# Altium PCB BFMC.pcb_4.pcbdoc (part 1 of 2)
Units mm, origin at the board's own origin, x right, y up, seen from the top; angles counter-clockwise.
Board outline 140.08 x 106.48 mm, 2 copper layers (Top Layer, Bottom Layer); 130 components, 63 nets, 367 pads, 103 vias.
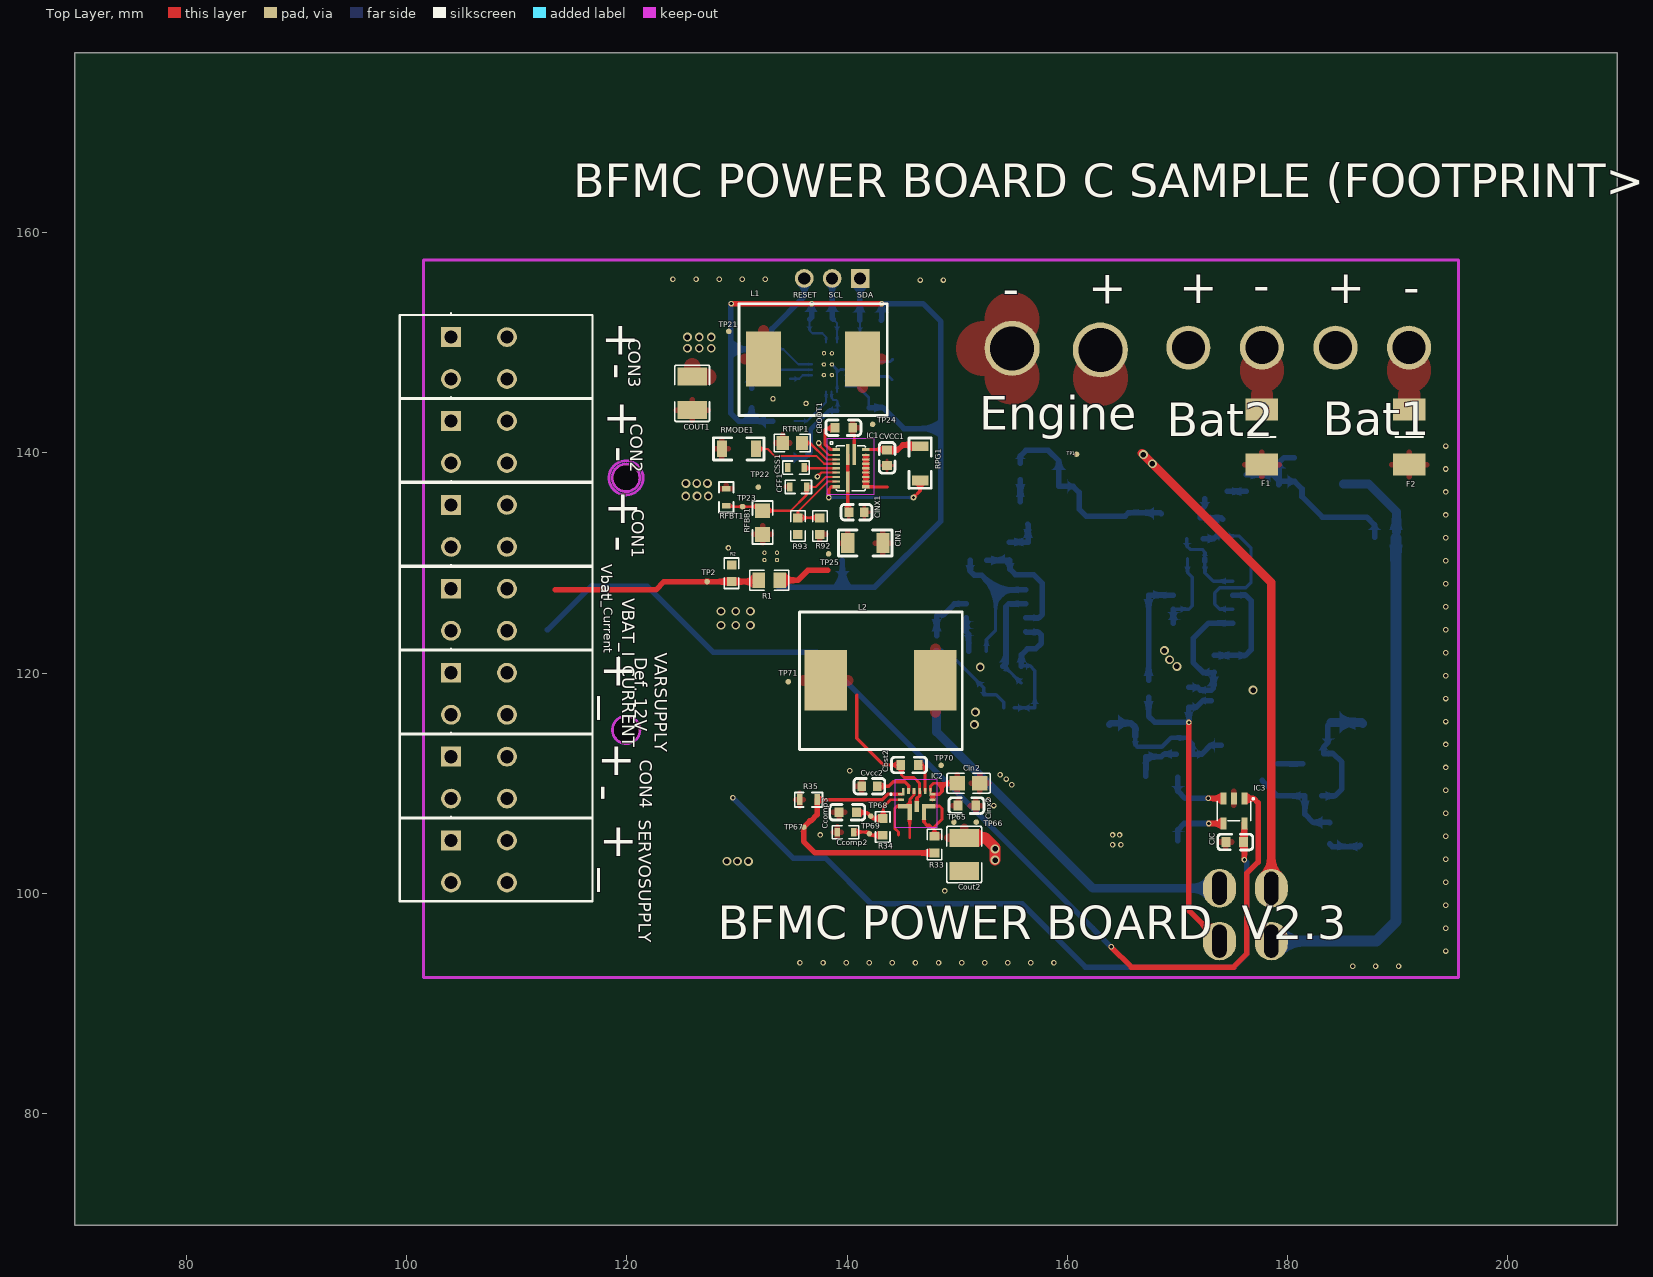
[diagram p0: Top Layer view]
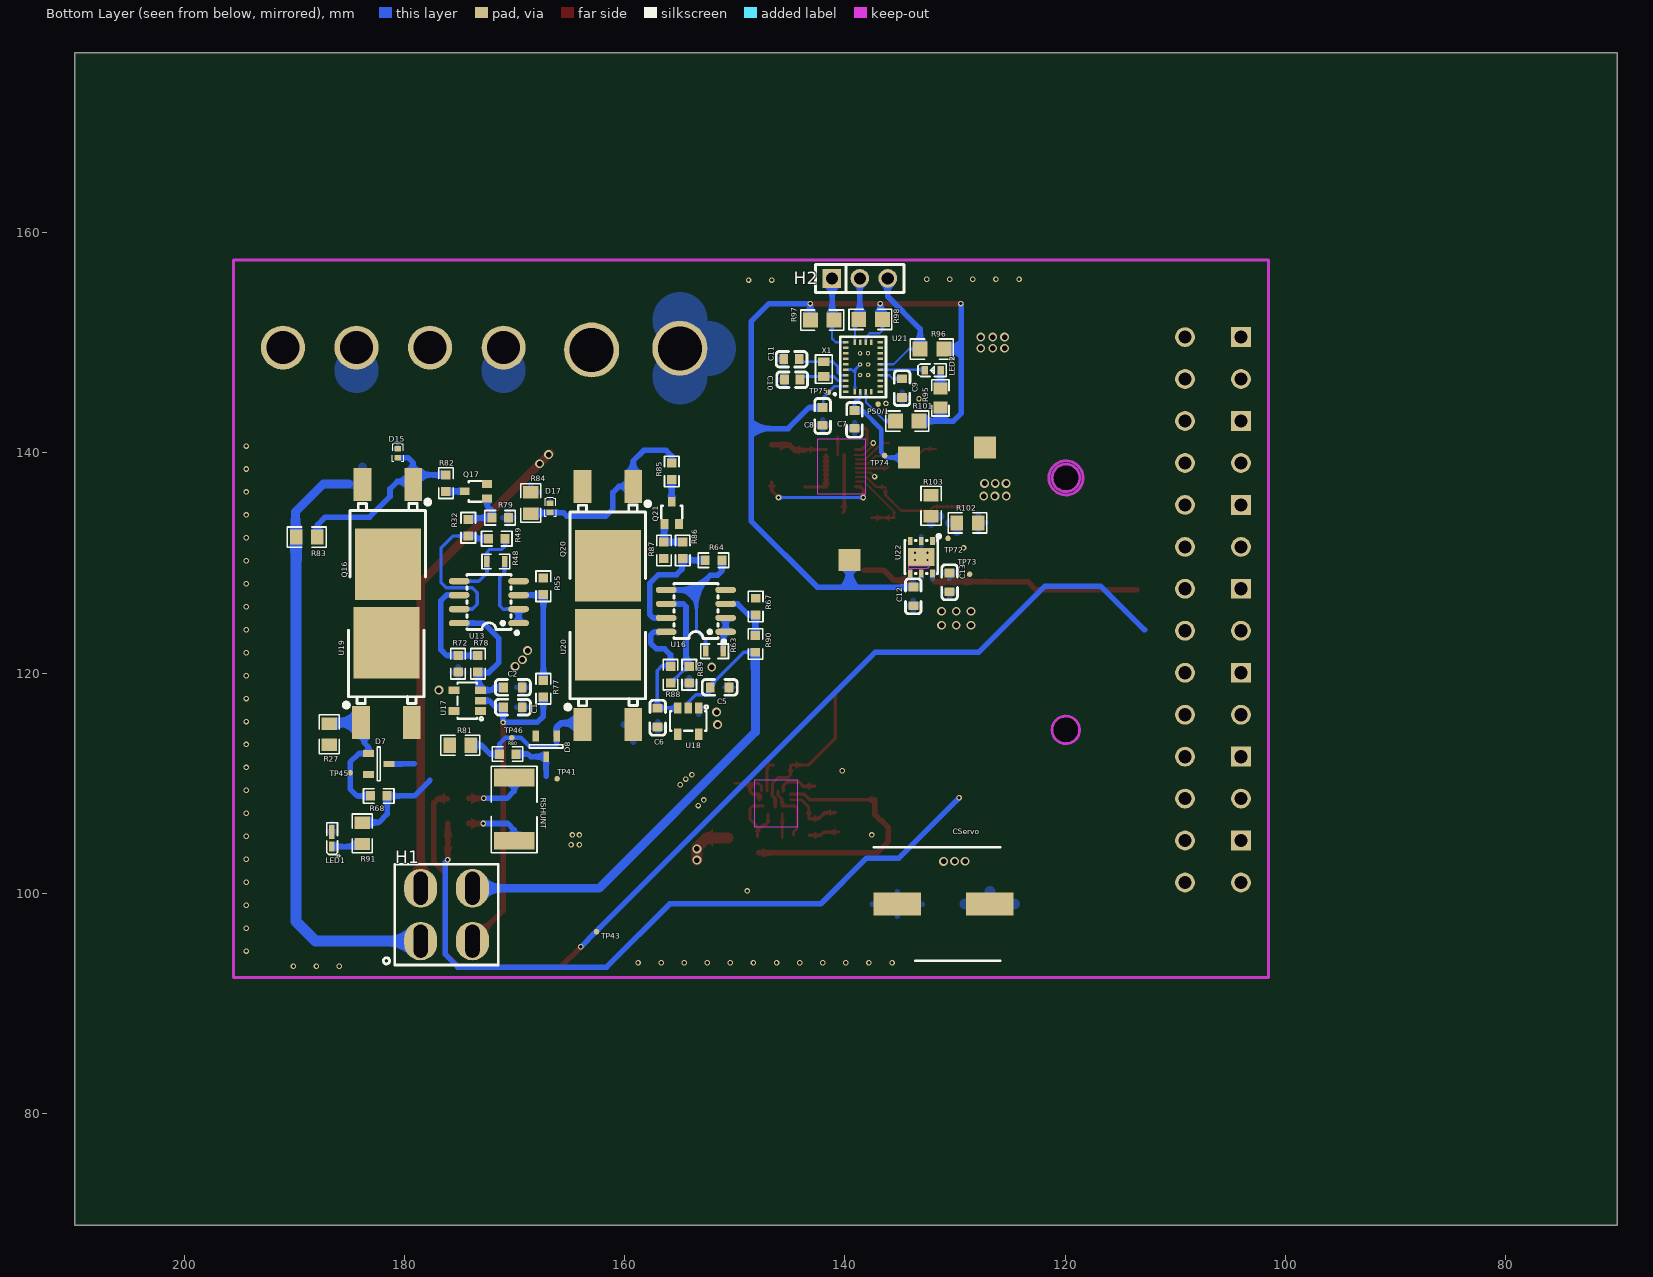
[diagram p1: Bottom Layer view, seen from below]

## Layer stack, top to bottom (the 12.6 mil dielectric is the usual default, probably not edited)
Top Layer: signal copper (thickness not stored)
Dielectric: dielectric 0.32, FR-4, Dk 4.8
Bottom Layer: signal copper (thickness not stored)

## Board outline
209.93,69.85 69.85,69.85 69.85,176.33 209.93,176.33
cut-out: 121.165,137.723 ccw(c119.915,137.711) 118.665,137.723 ccw(c119.915,137.735)
cut-out: 121.182,114.836 ccw(c119.932,114.836) 118.682,114.836 ccw(c119.932,114.836)

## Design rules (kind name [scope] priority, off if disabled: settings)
Clearance copperThickness1oz [All] p1: gap=0.178 ignorepadtopadclearanceinfootprint=FALSE except(0.102: Track-Track; 0.152: Track-SMDPad SMDPad-SMDPad Track-THPad SMDPad-THPad THPad-THPad Track-Via SMDPad-Via THPad-Via Via-Via Track-Fill SMDPad-Fill THPad-Fill Via-Fill Fill-Fill SMDPad-Region THPad-Region Via-Region Fill-Region Region-Region Track-Poly SMDPad-Poly THPad-Poly Via-Poly Fill-Poly Poly-Poly Track-Text SMDPad-Text THPad-Text Via-Text Fill-Text Region-Text Poly-Text Text-Text Track-Hole SMDPad-Hole THPad-Hole Via-Hole Fill-Hole Region-Hole Poly-Hole Text-Hole; 0.3: Track-Region Region-Poly Track-Sheet SMDPad-Sheet THPad-Sheet Via-Sheet Fill-Sheet Region-Sheet Poly-Sheet Text-Sheet Sheet-Hole)
Clearance copperThickness2oz [All] p1: gap=0.178 ignorepadtopadclearanceinfootprint=FALSE except(0.152: Track-SMDPad SMDPad-SMDPad Track-THPad SMDPad-THPad THPad-THPad Track-Via SMDPad-Via THPad-Via Via-Via Track-Fill SMDPad-Fill THPad-Fill Via-Fill Fill-Fill SMDPad-Region THPad-Region Via-Region Fill-Region Region-Region Track-Poly SMDPad-Poly THPad-Poly Via-Poly Fill-Poly Poly-Poly Track-Text SMDPad-Text THPad-Text Via-Text Fill-Text Region-Text Poly-Text Text-Text Track-Hole SMDPad-Hole THPad-Hole Via-Hole Fill-Hole Region-Hole Poly-Hole Text-Hole; 0.203: Track-Track; 0.3: Track-Region Region-Poly Track-Sheet SMDPad-Sheet THPad-Sheet Via-Sheet Fill-Sheet Region-Sheet Poly-Sheet Text-Sheet Sheet-Hole)
Clearance Supply-GND [All] p1: gap=0.178 ignorepadtopadclearanceinfootprint=FALSE except(0.5: Track-Track Track-SMDPad SMDPad-SMDPad Track-THPad SMDPad-THPad THPad-THPad Track-Via SMDPad-Via THPad-Via Via-Via Track-Fill SMDPad-Fill THPad-Fill Via-Fill Fill-Fill Track-Region SMDPad-Region THPad-Region Via-Region Fill-Region Region-Region Track-Poly SMDPad-Poly THPad-Poly Via-Poly Fill-Poly Region-Poly Poly-Poly Track-Text SMDPad-Text THPad-Text Via-Text Fill-Text Region-Text Poly-Text Text-Text Track-Sheet SMDPad-Sheet THPad-Sheet Via-Sheet Fill-Sheet Region-Sheet Poly-Sheet Text-Sheet Track-Hole SMDPad-Hole THPad-Hole Via-Hole Fill-Hole Region-Hole Poly-Hole Text-Hole Sheet-Hole)
DiffPairsRouting differentialPair [All] p1: maxuncoupledlength=10 maxlimit=5.9843 mostfreqgap=5.9843 toplayer_minwidth=5 toplayer_prefwidth=10 toplayer_maxwidth=100 bottomlayer_minwidth=5 bottomlayer_prefwidth=10 bottomlayer_maxwidth=100
PasteMaskExpansion pasteMaskExpansion [All] p1:
PlaneConnect innerPlane [All] p1: planeconnectstyle=Relief reliefexpansion=0.508 reliefentries=4 reliefconductorwidth=0.254 reliefairgap=0.254
PolygonConnect copperRegion [All] p1: connectstyle=Direct reliefentries=4 reliefconductorwidth=10 polygonreliefangle="90 Angle" airgapwidth=10
PolygonConnect copperRegion1 [All] p1: connectstyle=Relief reliefentries=4 reliefconductorwidth=10 polygonreliefangle="90 Angle" airgapwidth=10
PolygonConnect copperRegion2 [All] p1: connectstyle=Relief reliefentries=4 reliefconductorwidth=10 polygonreliefangle="90 Angle" airgapwidth=10
RoutingVias viaSize [All] p1: viastyle="Through Hole" holewidth=12.0078 minholewidth=11.811 maxholewidth=248.0314 width=24.0158 minwidth=19.685 maxwidth=393.7008
SolderMaskExpansion solderMaskExpansion [All] p1: useseparateexpansions=TRUE expansion=2.0079 expansionbottom=2.0079
Width copperThickness1oz [All] p1: maxlimit=100 minlimit=5 preferedwidth=10
Width copperThickness2oz [All] p1: maxlimit=100 minlimit=8 preferedwidth=10

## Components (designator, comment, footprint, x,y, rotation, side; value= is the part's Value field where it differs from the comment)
C1 "CAP_0201" C9 170.196,116.895 r180 bottom
C2 "CAP_0201" C9 170.196,118.695 r180 bottom
C5 "CAP_0201" C9 151.416,118.695 r180 bottom
C6 "CAP_0201" C9 156.996,115.995 r270 bottom
C7 "CAP_0201" Cbst2 139.116,142.935 r90 bottom
C8 "CAP_0201" Cbst2 142.02,143.4 r270 bottom
C9 "CAP_0201" C9 134.796,145.815 r90 bottom
C10 "CAP_0201" C0603 144.78,146.64 r0 bottom
C11 "CAP_0201" C0603 144.84,148.5 r0 bottom
C12 "CAP_0201" C9 133.776,126.915 r90 bottom
C13 "CAP_0201" C9 130.476,128.189 r90 bottom
CBOOT1 "EMK105 B7104KVHF" Cbst2 139.596,142.275 r0 top
Cbst2 "CAP_0201" Cbst2 145.559,111.645 r0 top
Ccomp2 "CAP_0201" "0603 0.5x0.8" 139.844,105.549 r0 top
Ccomp3 "CAP_0201" Cbst2 139.956,107.355 r0 top
CFF1 "C1005C0G1H220J" "0603 0.5x0.8" 135.557,136.904 r0 top
CIC "C2012X7S1C106K" Cbst2 175.296,104.655 r180 top
CIN1 "GCJ31CC71E106K" "Cin1 Aditome" 141.741,131.807 r0 top
Cin2 "CAP_0201" c0805 151.02,109.994 r180 top
CINX1 "GCM188C71A225K" C0603 140.852,134.601 r0 top
Cinx2 "CAP_0201" Cbst2 150.766,107.962 r0 top
CON1 "switch" "new connector" 106.56,133.361 r270 top
CON2 "switch" "new connector" 106.56,140.981 r270 top
CON3 "switch" "new connector" 106.56,148.601 r270 top
CON4 "switch" "new connector" 106.56,110.501 r270 top
COUT1 "EMK325ABJ107MM-T" C1210 125.919,145.4 r270 top
Cout2 "CAP_0201" C1210 150.626,103.519 r90 top
CServo "GCM188C71A225K" CAPAE1030X1050N 131.033,99.022 r180 bottom
CSS1 "C1608X7R1H154K" "0603 0.5x0.8" 135.353,138.657 r180 top
CVCC1 "GCM188C71A225K" C0603 143.619,139.54 r270 top
Cvcc2 "CAP_0201" C0603 142.026,109.719 r0 top
D7 "SZBZX84C18ET1G" SZBZX84C18ET1G 182.319,111.74 r270 bottom
D8 "SZBZX84C18ET1G" SZBZX84C18ET1G 167.119,113.34 r0 bottom
D15 "PZU6.8B2L,315" DFN1006-2L-RD 180.608,139.965 r270 bottom
D17 "PZU6.8B2L,315" DFN1006-2L-RD 166.765,135.012 r270 bottom
F1 "0451015.MRL" FUSC6127X294N 177.66,141.436 r270 top
F2 "0451015.MRL" FUSC6127X294N 191.047,141.436 r270 top
H1 "switch" M2021BB1W01 176.163,98.055 r0 bottom
H2 "HDR-M_2.54_1x3P" HDR-TH_3P-P2.54-V-M 138.636,155.835 r180 bottom
IC1 "TPS548A28RWWR" TPS548B28RWWR 140.344,138.603 r0 top
IC2 "TPS61288RQQR" TPS61288RQQR 146.326,108.119 r0 top
IC3 "INA180A2QDBVRQ1" ina180a2qdbvrq1 175.116,107.475 r180 top
L1 "IHLP4040DZERR47M11" IHLP4040DZERR47M11 136.896,148.455 r0 top
L2 "L_0402" "DR127-3R3-R (L2)" 143.026,119.332 r0 top
LED1 "19-213/Y2C-CQ2R2L/3T(CY)" LEDGREEN 186.576,105.015 r90 bottom
LED2 "TLMS1100-GS08" "LED2 RED" 132.096,147.495 r180 bottom
PS0/1 "Test-Point" Test-Point-0.5mm 136.98,144.42 r180 bottom
Q16 "IPD50P04P4-13" pg-to252-3_l6.3-w6.5-p4.57-ls10.0-br-cw 181.497,133.488 r90 bottom
Q17 "BC846W" SOT-323-3_L2.2-W1.3-P1.30-LS2.2-BR 173.499,136.5 r180 bottom
Q20 "IPD50P04P4-13" pg-to252-3_l6.3-w6.5-p4.57-ls10.0-br-cw 161.519,133.34 r90 bottom
Q21 "BC846W" SOT-323-3_L2.2-W1.3-P1.30-LS2.2-BR 155.719,134.54 r270 bottom
R1 "MCR03..PFX1051" R0805_NEW 132.923,128.425 r0 top
R2 "MCR03...PFX7680" r0603_new 129.494,129.06 r90 top
R27 "MCR03..PFX1002" R0805_NEW 186.819,114.44 r270 bottom
R32 "MCR03..PFX1002" R0603 174.199,133.2 r90 bottom
R33 "MCR03..PFX1002" R0603 147.926,104.419 r90 top
R34 "MCR03..PFX1002" R0603 143.226,106.019 r90 top
R35 "MCR03..PFX1002" R35 136.476,108.495 r180 top
R48 "Res_0603" R35 171.7,130.14 r0 bottom
R49 "Res_0603" R0603 171.599,132.2 r0 bottom
R55 "Res_0603" R0603 167.376,127.875 r270 bottom
R63 "Res_0603" R35 151.84,121.98 r0 bottom
R64 "Res_0603" R0603 151.919,130.24 r0 bottom
R67 "Res_0603" R0603 148.092,126.04 r270 bottom
R68 "Res_0603" R0603 182.319,108.84 r180 bottom
R72 "Res_0603" R0603 175.119,120.84 r270 bottom
R77 "Res_0603" R0603 167.376,118.575 r270 bottom
R78 "Res_0603" R0603 173.319,120.84 r270 bottom
R79 "Res_0603" R0603 171.299,134.1 r0 bottom
R80 "Res_0603" R0603 170.619,112.64 r180 bottom
R81 "MCR03..PFX1002" R0805_NEW 174.919,113.44 r0 bottom
R82 "Res_0603" R0603 176.216,137.242 r90 bottom
R83 "MCR03..PFX1002" R0805_NEW 188.863,132.345 r0 bottom
R84 "MCR03..PFX1002" R0805_NEW 168.519,135.44 r90 bottom
R85 "Res_0603" R0603 155.716,138.314 r90 bottom
R86 "MCR03..PFX1002" R0603 154.719,131.14 r270 bottom
R87 "Res_0603" R0603 156.419,131.14 r90 bottom
R88 "Res_0603" R0603 155.819,119.84 r270 bottom
R89 "Res_0603" R0603 154.119,119.84 r270 bottom
R90 "Res_0603" R0603 148.119,122.64 r90 bottom
R91 "Res_0603" R0805_NEW 183.819,105.44 r90 bottom
R92 "Res_0603" R0603 137.519,133.34 r270 top
R93 "Res_0603" R0603 135.519,133.34 r90 top
R95 "Res_0201" Rtrip 131.316,144.855 r90 bottom
R96 "Res_0201" "0805 dany2" 132.156,149.415 r180 bottom
R97 "Res_0201" "0805 dany2" 142.116,152.055 r180 bottom
R98 "Res_0201" "0805 dany2" 137.736,152.115 r180 bottom
R101 "Res_0201" "0805 dany2" 134.256,142.875 r0 bottom
R102 "Res_0201" R0805_NEW 128.856,133.635 r0 bottom
R103 "Res_0201" R0805_NEW 132.156,135.195 r90 bottom
RFBB1 "SMM0204 50 10K 1 %" "0805 dany2" 132.319,133.74 r270 top
RFBT1 "SMM0204 50 73K2 1 %" "0603 0.5x0.8" 129.019,135.96 r270 top
RMODE1 "SMM0204 50 30K1 1 %" "1206R aditome" 130.176,140.355 r180 top
RPG1 "SMM0204 50 30K1 1 %" "1206R aditome" 146.619,139.04 r90 top
RSHUNT "WSLP25122L500FEA" "WSLP25122L000FEA BUN" 170.019,107.64 r270 bottom
RTRIP1 "SMM0204 50 7K32 1 %" Rtrip 135.142,140.889 r180 top
SERVOSUPPLY "switch" "new connector" 106.56,102.881 r270 top
TP1 "Test-Point" Test-Point-0.5mm 160.824,139.862 r180 top
TP2 "Test-Point" Test-Point-0.5mm 127.275,128.302 r0 top
TP21 "Test-Point" Test-Point-0.5mm 129.244,151.024 r0 top
TP22 "Test-Point" Test-Point-0.5mm 131.924,136.887 r0 top
TP23 "Test-Point" Test-Point-0.5mm 130.502,135.109 r90 top
TP24 "Test-Point" Test-Point-0.5mm 142.306,142.586 r270 top
TP25 "Test-Point" Test-Point-0.5mm 138.306,130.821 r0 top
TP41 "Test-Point" Test-Point-0.5mm 166.127,110.398 r180 bottom
TP43 "Test-Point" Test-Point-0.5mm 162.546,96.516 r180 bottom
TP45 "Test-Point" Test-Point-0.5mm 184.919,110.94 r180 bottom
TP46 "Test-Point" Test-Point-0.5mm 170.246,114.114 r180 bottom
TP65 "Test-Point" Test-Point-0.5mm 149.694,106.459 r0 top
TP66 "Test-Point" Test-Point-0.5mm 151.718,106.457 r270 top
TP67 "Test-Point" Test-Point-0.5mm 136.057,106.01 r0 top
TP68 "Test-Point" Test-Point-0.5mm 142.141,107.01 r0 top
TP69 "Test-Point" Test-Point-0.5mm 142.019,105.408 r0 top
TP70 "Test-Point" Test-Point-0.5mm 148.526,111.619 r270 top
TP71 "Test-Point" Test-Point-0.5mm 134.65,119.211 r0 top
TP72 "Test-Point" Test-Point-0.5mm 130.627,132.227 r180 bottom
TP73 "Test-Point" Test-Point-0.5mm 128.667,128.967 r180 bottom
TP74 "Test-Point" Test-Point-0.5mm 136.38,139.74 r180 bottom
TP75 "Test-Point" Test-Point-0.5mm 141.48,145.5 r180 bottom
U13 "LT1490IS8#PBF" SO-8_L4.9-W3.9-P1.27-LS5.9-BL 172.319,126.44 r90 bottom
U16 "LT1490IS8#PBF" SO-8_L4.9-W3.9-P1.27-LS5.9-BL 153.519,125.64 r90 bottom
U17 "NCP715SN50T1G" TSOP-5_L3.0-W1.5-P0.95-BL 174.276,117.495 r90 bottom
U18 "NCP715SN50T1G" TSOP-5_L3.0-W1.5-P0.95-BL 154.219,115.64 r0 bottom
U19 "DMPH3010LK3-13" pg-to252-3_l6.3-w6.5-p4.57-ls10.0-br-cw 181.634,119.127 r270 bottom
U20 "DMPH3010LK3-13" pg-to252-3_l6.3-w6.5-p4.57-ls10.0-br-cw 161.519,118.94 r270 bottom
U21 "BNO055" LGA-28_L5.2-W3.8-P0.50-BL 138.336,147.795 r180 bottom
U22 "NCP708MU330TAG" DFN-6_L3.0-W3.0-P0.95-LS3.1-BL-EP 133.056,130.515 r0 bottom
VARSUPPLY "switch" "new connector" 106.56,118.121 r270 top
VBAT_I_CURRENT "switch" "new connector" 106.56,125.741 r270 top
X1 "ABS05-32.768kHz-T" OSC-SMD_2P-L1.6-W1.0 141.9,147.6 r270 bottom

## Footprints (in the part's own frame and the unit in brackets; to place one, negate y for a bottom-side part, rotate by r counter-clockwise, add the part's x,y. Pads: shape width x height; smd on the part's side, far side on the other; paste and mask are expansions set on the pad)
"0603 0.5x0.8" [mm]
  rect 0.5x0.8 smd: 1(-0.753,0) 2(0.753,0)
  silkscreen extent -1.2,-0.59 1.2,0.59
"0805 dany2" [mm]
  rect 1.35x1.377 smd: 1(-1,0) 2(1.15,0)
  silkscreen extent -1.89,-0.92 2.02,0.92
"1206R aditome" [mm]
  rect 0.9x1.5 smd: 1(-1.55,0) 2(1.55,0)
  silkscreen extent -2.27,-1.02 2.31,1.02
C9 [mm]
  rect 0.8x0.9 smd: 1(-0.8,0) 2(0.9,0)
  silkscreen extent -1.53,-0.71 1.64,0.72
C0603 [mm]
  rect 0.8x0.9 smd: 1(-0.7,0) 2(0.7,0)
  silkscreen extent -1.41,-0.71 1.39,0.72
c0805 [mm]
  rect 1.41x1.35 smd: 1(-1.03,0) 2(1.03,0)
  silkscreen extent -1.96,-0.9 1.96,0.9
C1210 [mm]
  rect 1.635x2.7 smd: 1(-1.517,0) 2(1.517,0)
  silkscreen extent -2.56,-1.58 2.56,1.58
CAPAE1030X1050N [mm]
  rect 4.3x2.05 smd: 1(-4.2,0) 2(4.2,0)
  silkscreen extent -6.35,-5.15 5.15,5.15
Cbst2 [mm]
  rect 0.8x0.9 smd: 1(-0.7,0) 2(0.9,0)
  silkscreen extent -1.53,-0.71 1.64,0.72
"Cin1 Aditome" [mm]
  rect 1.2x1.8 smd: 1(-1.7,0) 2(1.5,0)
  silkscreen extent -2.54,-1.17 2.33,1.17
DFN1006-2L-RD [mm]
  rect 0.5x0.6 smd: 1(-0.4,0) 2(0.4,0)
  silkscreen extent -0.9,-0.5 0.8,0.5
DFN-6_L3.0-W3.0-P0.95-LS3.1-BL-EP [mm]
  rect 0.45x0.701 smd: 1(-1.001,-1.476) 2(0,-1.476) 3(1.001,-1.476) 4(1.001,1.476) 5(0,1.476) 6(-1.001,1.476)
  rect 2.4x1.6 smd: 7(0,-0.025)
  silkscreen extent -1.75,-2.05 1.5,1.47
"DR127-3R3-R (L2)" [mm]
  rect 3.85x5.5 smd: 1(-4.975,0) 2(4.975,0)
  silkscreen extent -7.37,-6.28 7.42,6.22
FUSC6127X294N [mm]
  rect 2.02x2.95 smd: 1(-2.5,0) 2(2.5,0)
  silkscreen extent 0,-1.24 0,1.24
HDR-TH_3P-P2.54-V-M [mm]
  rect 1.7x1.7 hole 1.1: 1(-2.54,0)
  round 1.7 hole 1.1: 2(0,0) 3(2.54,0)
  silkscreen extent -4.02,-1.27 4.02,1.27
IHLP4040DZERR47M11 [mil]
  rect 125x195 smd: 1(-177.5,2.5) 2(177.5,2.5)
  silkscreen extent -265,-200 265,200
ina180a2qdbvrq1 [mm]
  rect 0.532x1.07 smd: 1(-0.95,-1.135) 2(0,-1.135) 3(0.95,-1.135) 4(0.95,1.135) 5(-0.95,1.135)
  silkscreen extent -1.9,-1.25 1.53,0.88
"LED2 RED" [mm]
  rect 0.6x0.8 smd: 1(-0.65,-0.003) 2(0.8,0.003)
  silkscreen extent -1.25,-0.57 1.32,0.58
LEDGREEN [mm]
  rect 1.3x0.5 smd: 1(0.55,0)
  rect 0.87x0.5 smd: 2(-0.765,0)
  silkscreen extent -1.74,-0.72 1.38,0.46
LGA-28_L5.2-W3.8-P0.50-BL [mm]
  rect 0.5x0.25 smd: 1(-1.563,-2.25) 6(1.563,-2.25) 7(1.563,-1.75) 8(1.563,-1.25) 9(1.563,-0.75) 10(1.563,-0.25) 11(1.563,0.25) 12(1.563,0.75) 13(1.563,1.25) 14(1.563,1.75) 15(1.563,2.25) 20(-1.563,2.25) 21(-1.563,1.75) 22(-1.563,1.25) 23(-1.563,0.75) 24(-1.563,0.25) 25(-1.563,-0.25) 26(-1.563,-0.75) 27(-1.563,-1.25) 28(-1.563,-1.75)
  rect 0.25x0.5 smd: 2(-0.75,-2.25) 3(-0.25,-2.25) 4(0.25,-2.25) 5(0.75,-2.25) 16(0.75,2.25) 17(0.25,2.25) 18(-0.25,2.25) 19(-0.75,2.25)
  silkscreen extent -2.66,-2.75 2.08,2.75
M2021BB1W01 [mm]
  oval 3x3.5 hole 1.3 slot 3 at 90 deg: 1(-2.35,-2.4) 2(2.35,-2.4) 3(-2.35,2.4) 4(2.35,2.4)
  silkscreen extent -4.7,-4.57 5.74,4.57
"new connector" [mm]
  rect 1.8x1.8 hole 1.2: 1(-1.905,-2.54)
  round 1.8 hole 1.2: 2(-1.905,2.54) 3(1.905,-2.54) 4(1.905,2.54)
  silkscreen extent -4.11,-7.19 3.61,10.31
OSC-SMD_2P-L1.6-W1.0 [mm]
  rect 0.8x1.06 smd: 1(-0.66,0) 2(0.66,0)
  silkscreen extent -1.29,-0.76 1.29,0.76
pg-to252-3_l6.3-w6.5-p4.57-ls10.0-br-cw [mm]
  rect 3x1.6 smd: 1(3.614,-2.299) 3(3.614,2.299)
  rect 6.5x6 smd: 2(-3.614,0.001)
  silkscreen extent -4.76,-3.83 2.24,3.43
R35 [mm]
  rect 0.5x1 smd: 1(-0.8,0) 2(0.8,0)
  silkscreen extent -1.28,-0.66 1.25,0.66
R0603 [mm]
  rect 0.806x0.864 smd: 1(-0.753,0) 2(0.753,0)
  silkscreen extent -1.39,-0.66 1.39,0.66
r0603_new [mm]
  rect 0.806x0.864 smd: 1(-0.753,0) 2(0.753,0)
  silkscreen extent -1.39,-0.66 1.39,0.66
R0805_NEW [mm]
  rect 1.133x1.377 smd: 1(-0.966,0) 2(0.966,0)
  silkscreen extent -1.76,-0.92 1.76,0.92
Rtrip [mm]
  rect 1.1x1.25 smd: 1(-0.753,0) 2(0.997,0)
  silkscreen extent -1.51,-0.79 1.77,0.79
SO-8_L4.9-W3.9-P1.27-LS5.9-BL [mm]
  oval 0.574x1.888 smd: 1(-1.905,-2.699) 2(-0.635,-2.699) 3(0.635,-2.699) 4(1.905,-2.699) 5(1.905,2.699) 6(0.635,2.699) 7(-0.635,2.699) 8(-1.905,2.699)
  silkscreen extent -2.94,-2.69 2.5,2
SOT-323-3_L2.2-W1.3-P1.30-LS2.2-BR [mm]
  rect 0.9x0.7 smd: 1(1.016,-0.66) 2(1.016,0.66) 3(-1.016,0)
  silkscreen extent -0.65,-0.95 0.48,0.95
SZBZX84C18ET1G [mm]
  rect 0.61x0.975 smd: 1(-0.95,-0.937) 2(0.95,-0.937)
  rect 0.523x0.975 smd: 3(0,0.937)
  silkscreen extent -1.54,-0.14 1.54,0.14
Test-Point-0.5mm [mm]
  round 0.5 smd: 1(0,0)
TPS548B28RWWR [mm]
  rect 0.7x0.3 smd: 1(-1.35,1.7) 9(-1.35,-1.7) 11(1.35,-1.7) 19(1.35,1.7)
  rect 0.7x0.2 smd: 2(-1.35,1.2) 3(-1.35,0.8) 4(-1.35,0.4) 5(-1.35,0) 6(-1.35,-0.4) 7(-1.35,-0.8) 8(-1.35,-1.2) 12(1.35,-1.2) 13(1.35,-0.8) 14(1.35,-0.4) 15(1.35,0) 16(1.35,0.4) 17(1.35,0.8) 18(1.35,1.2)
  rect 0.3x1.9 smd: 10(-0.3,-1.25) 20(0.3,1.25) 21(-0.3,1.25)
  silkscreen extent -1.9,-2.03 1.32,2.41
TPS61288RQQR [mm]
  rect 0.575x0.25 smd: 1(-1.413,0.875) 7(1.413,0.875)
  rect 0.55x0.25 smd: 2(-1.425,0.375) 6(1.425,0.375)
  rect 1.25x0.4 smd: 3(-1.075,-0.2) 5(1.075,-0.2)
  rect 0.4x1 smd: 4(0,-0.25)
  rect 0.25x0.55 smd: 8(0.75,1.175) 9(0.25,1.175) 10(-0.25,1.175) 11(-0.75,1.175)
  rect 0.225x0.45 smd: 12(-1.237,1.225) 15(1.237,1.225)
  rect 0.4x1.05 smd: 13(-0.65,-0.925) 14(0.65,-0.925)
  silkscreen extent -2.4,0.83 -2.3,0.92
TSOP-5_L3.0-W1.5-P0.95-BL [mm]
  rect 0.7x1 smd: 1(-0.95,-1.2) 2(0,-1.2) 3(0.95,-1.2) 4(0.95,1.2) 5(-0.95,1.2)
  silkscreen extent -1.8,-1.42 1.65,0.89
"WSLP25122L000FEA BUN" [mm]
  rect 1.6x3.68 smd: 1(-2.875,0) 2(2.875,0)
  silkscreen extent -3.91,-2.07 3.96,2.07

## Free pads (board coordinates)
  rect 2x2 smd far side: 1(127.26,140.46) 1(134.16,139.56) 1(139.56,130.26)
  round 0.4 hole 0.2: 1(132.48,130.26) 1(132.48,130.92) 1(133.62,130.26) 1(133.62,130.92) 1(137.89,149.045) 1(138.612,149.032) 2(137.88,148.02) 3(138.612,148.02) 4(137.88,147.06) 5(138.612,147.06)
  round 0.5 hole 0.3: 1(133.26,144.9) 1(136.26,144.48)
  round 5 hole 4: 22(154.983,149.49) 22(162.983,149.34)
  round 4 hole 3: 22(170.983,149.55) 22(177.663,149.55) 22(184.343,149.55) 22(191.022,149.55)

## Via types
v1: diameter 0.5, hole 0.3, Top Layer to Bottom Layer, 71 vias
v2: diameter 0.8, hole 0.5, Top Layer to Bottom Layer, 32 vias

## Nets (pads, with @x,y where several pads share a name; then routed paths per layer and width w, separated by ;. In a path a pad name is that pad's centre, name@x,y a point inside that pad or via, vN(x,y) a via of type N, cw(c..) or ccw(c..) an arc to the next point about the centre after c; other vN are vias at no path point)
$1N1788: D8.1 R80.1 R81.1 TP46.1 U20.1 | length 13.8
  Bottom Layer w0.4: D8.1@166.17,114.277 166.17,113.481 166.356,113.295 168.576,113.295 169.418,114.137 170.223,114.137 TP46.1@170.246,114.114 170.817,114.114 171.373,113.558 R80.1@171.373,112.64
  Bottom Layer w0.5: R80.1@171.373,112.64 172.206,112.64 173.006,113.44 R81.1@173.953,113.44
  Bottom Layer w0.6: U20.1@163.819,115.326 163.948,115.455 165.756,115.455 166.17,115.041 D8.1@166.17,114.277
$1N1798: D7.1 R27.1 R68.1 TP45.1 U19.1 | length 12.6
  Bottom Layer w0.5: R68.1@183.073,108.84 184.281,108.84 184.919,109.478 TP45.1@184.919,110.94 184.919,111.905 184.134,112.69 D7.1@183.257,112.69 183.257,113.276 183.633,113.653 183.633,115.213 U19.1@183.933,115.513
  Bottom Layer w0.8: U19.1@183.933,115.513 186.713,115.513 R27.1@186.819,115.406
$1N2164: Q16.2 U19.2
$1N2337: D15.2 Q16.1 R82.2 R83.1 | length 19
  Bottom Layer w0.5: R82.2@176.216,137.995 178.664,137.995 179.198,137.462 Q16.1@179.198,137.102 179.22,137.124 Q16.1@179.22,137.4 ; D15.2@180.608,139.565 179.666,139.565 179.22,139.12 Q16.1@179.22,137.4 ; R83.1@187.897,132.345 187.897,133.442 187.18,134.16 183.154,134.16 181.3,136.014 181.3,136.721 180.621,137.4 Q16.1@179.22,137.4
$1N2412: Q17.3 R82.1 | length 1.7
  Bottom Layer w0.5: Q17.3@174.515,136.5 176.205,136.5 R82.1@176.216,136.489
$1N2516: Q17.1 R32.2 R79.2 | length 4
  Bottom Layer w0.5: Q17.1@172.483,135.84 172.483,135.184 172.053,134.753 R79.2@172.053,134.1 173.953,134.1 R32.2@174.099,133.953
$1N20674: R55.2 R77.1 U13.3 | length 10
  Bottom Layer w0.5: R77.1@167.376,119.329 167.376,127.062 167.389,127.075 U13.3@169.62,127.075
$1N20931: R48.1 U13.1 U13.2 | length 7.6
  Bottom Layer w0.3: U13.2@169.62,125.805 171.037,125.805 171.337,126.105 171.337,128.705 170.9,129.143 R48.1@170.9,130.38
  Bottom Layer w0.5: U13.1@169.62,124.535 U13.2@169.62,125.805
$1N20946: R48.2 R49.1 U13.5 | length 7.3
  Bottom Layer w0.3: R49.1@170.846,132.2 170.846,131.534 171.16,131.22 172.24,131.22 172.48,130.98 R48.2@172.48,130.36 ; R48.2@172.5,130.14 172.48,130.16 172.48,129.12 173.255,128.345 U13.5@175.018,128.345
  Bottom Layer w0.5: R48.2@172.48,130.16 R48.2@172.48,130.36
$1N20962: R32.1 R49.2 U13.7 | length 14.5
  Bottom Layer w0.3: R32.1@174.199,132.447 175.573,132.447 176.671,131.348 176.671,128.231 176.181,127.74 173.839,127.74 173.369,127.27 173.369,126.264 173.828,125.805 U13.7@175.018,125.805
  Bottom Layer w0.5: R49.2@172.353,132.2 173.299,132.2 173.546,132.447 R32.1@174.199,132.447
$1N21052: R72.1 R78.1 U13.6 | length 9.9
  Bottom Layer w0.5: R78.1@173.319,121.593 R72.1@175.119,121.593 176.154,121.593 176.676,122.115 176.676,126.575 176.176,127.075 U13.6@175.018,127.075
$1N27791: Q20.2 U20.2
$1N27792: D17.2 Q20.1 R84.1 R85.2 | length 18.5
  Bottom Layer w0.5: R85.2@155.716,139.067 155.716,139.719 156.216,140.219 158.256,140.219 159.22,139.255 Q20.1@159.22,136.954 160.505,136.954 161.05,136.409 161.05,134.885 161.685,134.25 165.241,134.25 165.541,134.55 168.443,134.55 R84.1@168.519,134.474
$1N27793: Q21.3 R85.1 | length 2
  Bottom Layer w0.5: R85.1@155.716,137.561 155.719,137.558 Q21.3@155.719,135.556
$1N27799: Q21.1 R86.1 R87.2 | length 3.3
  Bottom Layer w0.5: R86.1@154.719,131.893 R87.2@156.419,131.893 156.419,133.484 Q21.1@156.38,133.524
$1N27802: R63.1 U16.1 U16.2 | length 3.1
  Bottom Layer w0.5: U16.2@150.82,125.005 U16.1@150.82,123.735 151.04,123.516 R63.1@151.04,121.98
$1N27807: R63.2 R64.1 U16.5 | length 12.6
  Bottom Layer w0.3: R63.2@152.64,121.98 152.64,123.02 153.461,123.841 153.461,127.54 ; U16.5@156.213,127.54 U16.5@156.218,127.545
  Bottom Layer w0.5: R64.1@151.166,130.24 151.166,129.265 151.536,128.895 152.196,128.895 153.546,127.545 U16.5@156.218,127.545
$1N27811: R64.2 R86.2 U16.7 | length 11
  Bottom Layer w0.3: R86.2@154.573,130.24 R86.2@154.719,130.387
  Bottom Layer w0.5: R64.2@152.673,130.24 154.573,130.24 154.78,130.24 154.78,129.44 155.28,128.94 156.919,128.94 157.719,128.14 157.719,125.331 157.393,125.005 U16.7@156.218,125.005
$1N27822: R67.2 R90.2 U16.3 | length 4.9
  Bottom Layer w0.3: R67.2@148.119,125.187 R67.2@148.219,125.287
  Bottom Layer w0.5: R90.2@148.119,123.393 R67.2@148.119,125.187 ; R67.2@148.219,125.287 148.738,125.287 149.726,126.275 U16.3@150.82,126.275
$1N32332: R88.2 R89.1 U16.6 | length 9.8
  Bottom Layer w0.3: R89.1@154.119,120.593 154.313,120.593 R88.2@155.819,119.087
  Bottom Layer w0.5: R89.1@154.119,120.593 154.419,120.893 154.419,126.04 154.654,126.275 U16.6@156.218,126.275
$1N40141: LED1.2 R91.1 | length 2.9
  Bottom Layer w0.5: R91.1@183.819,104.474 184.058,104.235 186.441,104.235 LED1.2@186.576,104.37
$2N28: F1.1 pad.22@177.663,149.55
$2N30: F2.1 pad.22@191.022,149.55
$3N2936: Ccomp2.2 R34.1 TP69.1 | length 2.8
  Top Layer w0.3: Ccomp2.2@140.538,105.555 141.918,105.555 142.208,105.266 R34.1@143.226,105.266
$5N394: C9.2 U21.9 | length 2.1
  Bottom Layer w0.2: C9.2@134.796,146.715 135.636,146.715 135.966,147.045 U21.9@136.773,147.045
$5N959: LED2.2 R95.2 | length 1.7
  Bottom Layer w0.5: LED2.2@131.296,147.499 131.316,147.479 R95.2@131.316,145.852
$5N968: LED2.1 U21.10 | length 4
  Bottom Layer w0.2: LED2.1@132.776,147.492 132.829,147.545 U21.10@136.773,147.545
$5N2144: R101.2 U21.4 | length 4.5
  Bottom Layer w0.2: R101.2@135.222,142.875 136.356,142.875 138.086,144.605 U21.4@138.086,145.545
+3V3: C8.1 C12.2 pad.1@139.56,130.26 R95.1 R96.2 R97.1 R98.2 R101.1 TP75.1 U21.17 U21.28 U22.4 U22.5 | length 91.3
  Top Layer w0.5: v1(129.456,153.555) v1(136.776,153.555) v1(143.136,153.555)
  Bottom Layer w0.2: R98.2@136.586,152.115 136.586,151.105 136.836,150.855 137.736,150.855 138.086,150.505 U21.17@138.086,150.045
  Bottom Layer w0.254: U21.28@139.899,146.045 140.935,146.045 TP75.1@141.48,145.5 141.96,145.02 141.96,144.16 C8.1@142.02,144.1
  Bottom Layer w0.5: v1(129.456,153.555) 129.445,153.545 129.445,149.399 ; R96.2@131.006,149.415 129.462,149.415 129.445,149.399 ; R95.1@131.316,144.102 131.316,142.881 131.31,142.875 ; R101.1@133.256,142.875 131.31,142.875 ; C12.2@133.776,127.815 133.791,127.8 139.56,127.8 pad.1@139.56,130.26 ; R98.2@136.586,152.115 136.77,152.299 136.77,153.549 v1(136.776,153.555) ; 139.609,127.8 142.5,127.8 148.5,133.8 148.5,142.173 ; C8.1@142.02,144.1 143.24,144.1 145.14,142.2 148.473,142.2 148.5,142.173 ; R97.1@143.082,152.055 143.136,152.109 v1(143.136,153.555) 146.865,153.555 148.5,151.92 148.5,142.173 ; 129.445,149.399 129.445,143.569 130.139,142.875 131.31,142.875
+5V: C13.2 CFF1.1 CIC.1 Cin2.2 Cinx2.1 CON1.1 CON1.2 CON2.1 CON2.2 CON3.1 CON3.2 CON4.1 CON4.2 COUT1.1 CServo.2 IC2.6 IC2.7 IC2.15 IC3.5 L1.1 L2.2 pad.1@127.26,140.46 R102.1 RFBT1.1 SERVOSUPPLY.1 SERVOSUPPLY.2 TP21.1 TP22.1 TP70.1 TP73.1 U22.6 | length 70.6
  Top Layer w0.254: IC2.15@147.563,109.344 147.563,109.713 147.845,109.994 Cin2.2@149.99,109.994
  Top Layer w0.3: IC2.7@147.739,108.994 IC2.7@147.751,108.982 ; IC2.6@147.751,108.494 IC2.7@147.751,108.982 ; 148.591,109.925 148.597,109.919 148.597,109.232 148.347,108.982 IC2.7@147.751,108.982
  Top Layer w0.5: IC3.5@176.066,106.34 176.066,104.845 175.996,104.775 176.076,104.695 v1(176.076,103.035)
  Bottom Layer w0.5: v1(129.619,108.66) 135.079,103.2 138.025,103.2 142.176,99.048 155.886,99.048 161.635,93.3 175.14,93.3 176.28,94.44 176.28,102.831 v1(176.076,103.035)
  other v2: 129.079,102.9 130.036,102.9 131.033,102.886 128.538,124.344 129.872,124.344 131.205,124.344 128.538,125.614 129.872,125.614 131.205,125.614 125.333,136.068 126.361,136.068 127.388,136.068 125.35,137.222 126.33,137.222 127.31,137.222 125.49,149.49 126.57,149.49 127.649,149.49 125.49,150.506 126.57,150.506 127.649,150.506
+VCC2: C2.1 R78.2 U13.8 U17.3 | length 12.5
  Bottom Layer w0.5: C2.1@170.996,118.695 171.816,118.695 172.066,118.445 U17.3@173.076,118.445 173.259,118.628 R78.2@173.259,120.026 ; R78.2@173.319,120.087 R78.2@173.259,120.026 ; U13.8@175.018,124.535 172.814,124.535 171.419,123.14 171.419,120.96 172.353,120.026 R78.2@173.259,120.026
+VCC3: C6.1 R88.1 U16.8 U18.3 | length 12.3
  Bottom Layer w0.3: U18.3@155.169,116.84 157.038,116.84 157.038,120.228 156.605,120.661 155.887,120.661 R88.1@155.819,120.593
  Bottom Layer w0.5: R88.1@155.819,120.593 155.819,121.653 156.351,122.185 157.113,122.185 157.621,122.693 157.621,123.455 157.367,123.709 156.244,123.709 U16.8@156.218,123.735
ADC1: R1.1 R2.1 TP2.1 VBAT_I_CURRENT.1 VBAT_I_CURRENT.2 | length 18.8
  Top Layer w0.5: 113.5,127.56 122.62,127.56 123.355,128.295 R2.1@129.483,128.295 ; R2.1@129.494,128.307 R2.1@129.483,128.295 ; R1.1@131.957,128.425 131.827,128.295 R2.1@129.483,128.295
BOOT: CBOOT1.1 IC1.1 | length 3.4
  Top Layer w0.3: CBOOT1.1@138.836,142.275 138.776,142.215 138.156,142.215 137.976,142.035 137.976,140.775 138.448,140.303 IC1.1@138.994,140.303
BST: Cbst2.2 IC2.8 | length 2.8
  Top Layer w0.254: Cbst2.2@146.459,111.645 146.829,111.645 147.076,111.398 IC2.8@147.076,109.294
COMP: Ccomp3.2 IC2.2 R34.2 TP68.1 | length 5.6
  Top Layer w0.254: R34.2@143.226,106.772 143.27,106.816 143.27,107.834 143.93,108.494 IC2.2@144.901,108.494
  Top Layer w0.3: Ccomp3.2@140.856,107.355 140.892,107.319 141.826,107.319 142.373,106.772 R34.2@143.226,106.772
EN: IC1.8 R92.1 R93.2 | length 7.2
  Top Layer w0.2: R93.2@135.519,134.093 135.519,134.64 138.282,137.403 IC1.8@138.994,137.403
  Top Layer w0.254: R93.2@135.519,134.093 R92.1@137.519,134.093
EN3V3: R102.2 R103.1 TP72.1 U22.1
FB: CFF1.2 IC1.7 RFBB1.1 RFBT1.2 TP23.1 | length 11.9
  Top Layer w0.2: RFBT1.2@129.019,135.207 129.199,135.207 129.297,135.109 TP23.1@130.502,135.109 131.95,135.109 RFBB1.1@132.319,134.74 134.881,134.74 136.311,136.17 CFF1.2@136.311,136.904 137.165,136.904 138.064,137.803 IC1.7@138.994,137.803
FB_1: IC2.1 IC2.12 R33.1 R35.1 TP67.1 | length 24.4
  Top Layer w0.3: R35.1@137.276,108.495 143.203,108.495 143.726,109.019 144.888,109.019 IC2.1@144.913,108.994
  Top Layer w0.5: R35.1@137.276,108.495 137.276,107.145 136.696,106.565 136.612,106.565 TP67.1@136.057,106.01 136.034,105.987 136.034,104.712 137.08,103.666 R33.1@147.826,103.666
GND: 
GPIO6: H2.3 R96.1 U21.11 | length 11.8
  Bottom Layer w0.2: R96.1@133.156,149.415 134.196,149.415 135.566,148.045 U21.11@136.773,148.045
  Bottom Layer w0.5: R96.1@133.156,149.415 133.156,151.255 136.116,154.215 H2.3@136.116,155.095 ; H2.3@136.096,155.115 H2.3@136.116,155.095 ; H2.3@136.116,155.815 H2.3@136.116,155.095
ISHUNT: IC3.1 TP43.1 VBAT_I_CURRENT.3 VBAT_I_CURRENT.4 | length 95.6
  Top Layer w0.5: v1(163.971,95.134) 165.805,93.3 175.091,93.3 176.28,94.488 176.28,101.799 177.306,102.826 177.306,108.215 176.933,108.588 IC3.1@176.088,108.588
  Bottom Layer w0.3: TP43.1@162.546,96.516 TP43.1@162.589,96.516
  Bottom Layer w0.5: 112.743,123.917 112.797,123.917 116.765,127.885 121.822,127.885 127.841,121.866 137.24,121.866 162.589,96.516 v1(163.971,95.134)
MODE: IC1.4 RMODE1.1 | length 7.8
  Top Layer w0.2: RMODE1.1@131.726,140.355 132.756,140.355 133.416,139.695 137.22,139.695 137.912,139.003 IC1.4@138.994,139.003
OUT_BATT: CIN1.1 CINX1.1 IC1.10 IC1.21 IC3.4 pad.22@162.983,149.34 R1.2 R92.2 RSHUNT.2 TP1.1 TP25.1 | length 15.4
  Top Layer w0.3: IC1.21@140.044,139.853 IC1.10@140.044,137.353 140.044,134.709 CINX1.1@140.152,134.601
  Top Layer w0.5: R1.2@133.89,128.425 135.526,128.425 136.416,129.315 138.216,129.315 ; v1(172.836,106.335) 174.161,106.335 IC3.4@174.166,106.34
  Bottom Layer w0.5: RSHUNT.2@170.019,104.765 170.019,105.754 170.601,106.335 v1(172.836,106.335)
  other v1: 164.098,104.405 164.86,104.405 164.098,105.294 164.733,105.294
OUT_BATT1: D15.1 H1.4 pad.22@184.343,149.55 Q16.3 R83.2 | length 54.6
  Bottom Layer w0.8: 185.053,137.171 187.349,137.171 189.886,134.634 R83.2@189.886,132.84
  Bottom Layer w1: H1.4@178.513,95.655 188.063,95.655 189.827,97.419 R83.2@189.827,132.282
OUT_BATT2: D17.1 H1.2 pad.22@170.983,149.55 Q20.3 R84.2 | length 44.4
  Top Layer w0.8: v2@166.765,139.965 v2(167.719,139.011) 178.513,128.217 H1.2@178.513,100.455
  other v2: 166.892,139.838
PGOOD: IC1.9 RPG1.1 | length 10.8
  Top Layer w0.3: v1@138.312,135.956 138.312,136.649 138.566,136.903 IC1.9@138.994,136.903 ; v1(146.019,135.94) 146.619,136.54 RPG1.1@146.619,137.34
  Bottom Layer w0.3: v1(138.319,135.94) v1(146.019,135.94)
SCK/SCL: H2.2 R98.1 U21.19 | length 6
  Bottom Layer w0.2: R98.1@138.736,152.115 139.086,151.765 U21.19@139.086,150.045
  Bottom Layer w0.5: H2.2@138.636,155.835 138.636,152.215 R98.1@138.736,152.115
SDI/SDA: H2.1 R97.2 U21.20 | length 6.9
  Bottom Layer w0.2: U21.20@139.899,150.045 140.826,150.045 141.156,150.375 141.156,152.049 R97.2@141.15,152.055
  Bottom Layer w0.5: R97.2@141.15,152.055 H2.1@141.15,155.089 ; H2.1@141.15,155.809 H2.1@141.15,155.089 ; H2.1@141.176,155.115 H2.1@141.15,155.089
SS_REFIN: CSS1.1 IC1.5 | length 3
  Top Layer w0.2: CSS1.1@136.053,138.717 136.166,138.603 IC1.5@138.994,138.603
SW: CBOOT1.2 IC1.20 L1.2 TP24.1 | length 1.6
  Top Layer w0.254: IC1.20@140.644,139.853 140.644,141.44
SW_1: Cbst2.1 IC2.4 IC2.9 L2.1 TP71.1 | length 14
  Top Layer w0.254: Cbst2.1@144.859,111.645 144.924,111.58 144.924,110.756 145.178,110.502 146.067,110.502 146.576,109.993 IC2.9@146.576,109.294
  Top Layer w0.3: 140.857,117.974 140.857,114.088 143.3,111.645 Cbst2.1@144.859,111.645 ; IC2.4@146.326,107.869 146.326,108.619 146.576,108.869 IC2.9@146.576,109.294
TRIP: IC1.3 RTRIP1.1 | length 3.6
  Top Layer w0.2: RTRIP1.1@135.984,140.87 136.003,140.889 136.626,140.889 138.112,139.403 IC1.3@138.994,139.403
UBATT: D7.3 D8.3 IC3.3 R68.2 R80.2 R91.2 RSHUNT.1 TP41.1 U19.3 U20.3 | length 21.3
  Top Layer w0.5: v1(172.776,108.615) 174.161,108.615 IC3.3@174.166,108.61
  Bottom Layer w0.5: 167.119,110.628 D8.3@167.119,112.403 168.54,112.403 168.777,112.64 R80.2@169.866,112.64 ; RSHUNT.1@170.019,110.515 170.019,109.279 170.683,108.615 v1(172.776,108.615) ; 177.687,110.247 179.094,108.84 R68.2@181.566,108.84 181.566,107.193 182.319,106.44 183.786,106.44 R91.2@183.819,106.406 ; 179.084,111.74 D7.3@181.382,111.74
VBATT1: C1.1 H1.3 R77.2 U17.2 | length 30.4
  Top Layer w0.5: v1(171.036,115.515) 171.036,98.433 H1.3@173.813,95.655
  Bottom Layer w0.5: R77.2@167.376,117.822 167.376,116.075 167.936,115.515 v1(171.036,115.515) 171.036,116.895 C1.1@170.996,116.895 ; C1.1@170.996,116.895 171.703,116.895 172.303,117.495 U17.2@173.076,117.495
VBATT2: C5.1 H1.1 R90.1 U18.2 | length 47.7
  Bottom Layer w0.3: R90.1@148.119,121.887 149.173,121.887 152.394,118.666 152.394,118.04 152.819,118.04 153.519,118.04 154.219,117.34 U18.2@154.219,116.84
  Bottom Layer w0.8: R90.1@148.119,121.887 148.119,114.64 162.304,100.455 H1.1@173.813,100.455
VCC: CVCC1.1 IC1.19 RPG1.2 | length 5.2
  Top Layer w0.3: IC1.19@141.694,140.303 143.557,140.303 CVCC1.1@143.62,140.24
  Top Layer w0.5: CVCC1.1@143.62,140.24 144.563,140.24 145.051,140.728 146.608,140.728 RPG1.2@146.619,140.74
VCCBOOST: Cvcc2.2 IC2.11 | length 3.6
  Top Layer w0.3: Cvcc2.2@142.726,109.719 143.76,109.719 144.16,110.119 145.226,110.119 145.576,109.769 IC2.11@145.576,109.294
VDD: C7.2 pad.1@134.16,139.56 TP74.1 U21.3 | length 10
  Bottom Layer w0.2: U21.3@138.586,145.545 138.586,144.965 138.756,144.795 138.996,144.795 139.116,144.675 C7.2@139.116,143.835
  Bottom Layer w0.4: pad.1@134.16,139.56 136.2,139.56 TP74.1@136.38,139.74 136.68,140.04 136.68,142.14 138.375,143.835 C7.2@139.116,143.835
VOUT1: Cout2.2 IC2.5 IC2.14 R33.2 TP65.1 TP66.1 VARSUPPLY.1 VARSUPPLY.2 | length 10.3
  Top Layer w0.254: IC2.5@147.401,107.919 148.392,107.919 148.604,107.707 148.604,106.722 147.763,105.881
  Top Layer w0.3: IC2.14@146.976,107.194 146.976,106.437 147.23,106.183 147.461,106.183 147.763,105.881 147.926,105.718 R33.2@147.926,105.172
  Top Layer w1: Cout2.2@150.626,105.036 152.545,105.036 153.43,104.151 v2(153.43,104.024) v2(153.43,103.008)
XIN32: C10.1 U21.27 X1.2 | length 4.5
  Bottom Layer w0.254: U21.27@139.899,146.545 140.605,146.545 141,146.94 X1.2@141.9,146.94 143.779,146.94 C10.1@144.08,146.64
XOUT32: C11.1 U21.26 X1.1 | length 5.2
  Bottom Layer w0.254: U21.26@139.899,147.045 140.385,147.045 140.64,147.3 140.64,147.84 141.06,148.26 X1.1@141.9,148.26 143.9,148.26 C11.1@144.14,148.5
pads on no net: C1.2 C2.2 C5.2 C6.2 C7.1 C8.2 C9.1 C10.2 C11.2 C12.1 C13.1 Ccomp2.1 Ccomp3.1 CIC.2 CIN1.2 Cin2.1 CINX1.2 Cinx2.2 CON1.3 CON1.4 CON2.3 CON2.4 CON3.3 CON3.4 CON4.3 CON4.4 COUT1.2 Cout2.1 CServo.1 CSS1.2 CVCC1.2 Cvcc2.1 D7.2 D8.2 F1.2 F2.2 IC1.2 IC1.6 IC1.11 IC1.12 IC1.13 IC1.14 IC1.15 IC1.16 IC1.17 IC1.18 IC2.3 IC2.10 IC2.13 IC3.2 LED1.1 PS0/1.1 Q17.2 Q21.2 R2.2 R27.2 R35.2 R55.1 R67.1 R72.2 R79.1 R81.2 R87.1 R89.2 R93.1 R103.2 RFBB1.2 RMODE1.2 RTRIP1.2 SERVOSUPPLY.3 SERVOSUPPLY.4 U13.4 U16.4 U17.1 U17.4 U17.5 U18.1 U18.4 U18.5 U21.1 U21.2 U21.5 U21.6 U21.7 U21.8 U21.12 U21.13 U21.14 U21.15 U21.16 U21.18 U21.21 U21.22 U21.23 U21.24 U21.25 U22.2 U22.3 U22.7 VARSUPPLY.3 VARSUPPLY.4
copper on no net: | length 20.3
  Top Layer w0.2: v1(137.296,137.841) 137.658,138.203 138.994,138.203 ; v1@137.421,140.887 137.421,140.712 138.33,139.803 139.121,139.803
  Top Layer w0.254: 141.694,136.903 143.659,136.903 ; 144.667,105.294 144.667,105.548 144.318,105.897 144.318,107.707 144.53,107.919 145.251,107.919 145.699,107.919 145.699,108.54 146.076,108.917 146.076,109.294 ; 145.676,107.194 145.676,105.04 145.683,105.04
  Top Layer w0.3: 141.694,136.903 141.694,137.403 141.694,137.803 141.694,138.203 141.694,138.603 141.694,139.003 141.694,139.403 141.694,139.803
  Bottom Layer w0.2: 139.086,145.545 139.086,147.285 139.356,147.555 139.889,147.555 139.899,147.545
  Bottom Layer w0.254: 138.612,148.02 139.086,147.547 139.086,147.285
  other v1: 185.895,93.36 187.98,93.36 190.064,93.36 135.71,93.702 137.807,93.702 139.904,93.702 142.001,93.702 144.098,93.702 146.195,93.702 148.292,93.702 150.389,93.702 152.486,93.702 154.583,93.702 156.68,93.702 158.777,93.702 194.361,94.749 194.361,96.834 194.361,98.919 148.858,100.214 194.361,101.004 194.361,103.088 194.361,105.173 137.558,105.295 194.361,107.258 153.306,107.962 152.798,108.47 194.361,109.342 154.954,109.866 154.446,110.374 153.876,110.775 140.226,111.119 194.361,111.427 194.361,113.512 194.361,115.596 194.361,117.681 194.361,119.766 194.361,121.85 194.361,123.935 194.361,126.02 194.361,128.104 194.361,130.189 129.216,131.355 194.361,132.274 194.361,134.358 194.361,136.443 194.361,138.528 194.361,140.613 137.423,140.889 146.643,155.687 148.74,155.687 124.174,155.747 126.271,155.747 128.368,155.747 130.465,155.747 132.562,155.747
  other v2: 151.552,115.318 151.639,116.46 176.856,118.455 152.08,120.54 169.939,120.6 169.279,121.2 168.799,122.04

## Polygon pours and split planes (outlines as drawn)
no net on Top Layer (solid, remove dead copper, pour order 34): 84.9,83.76 203.16,83.76 203.16,162.24 84.9,162.24
no net on Bottom Layer (solid, remove dead copper, pour order 78): 76.2,76.2 203.58,76.2 203.58,169.98 76.2,169.98
OUT_BATT1 on Bottom Layer (solid, remove dead copper, pour order 36): 180.419,140.136 180.419,143.777 182.22,145.713 182.22,150.29 186.539,150.29 186.539,137.11 185.419,135.99 182.846,135.99 182.846,139.509 182.219,140.136
SW on Top Layer (solid, remove dead copper): 140.303,141.369 141.212,141.376 141.695,141.859 142.584,141.859 143.892,143.167 143.892,149.919 143.056,150.879 139.997,150.879 139.76,150.592 139.831,142.753
$1N27791 on Bottom Layer (solid, remove dead copper, pour order 38): 158.536,132.719 158.719,132.719 158.719,132.74 158.619,132.84 158.619,132.802
OUT_BATT on Top Layer (solid, remove dead copper, pour order 2): 165.732,152.14 165.732,127.485 150.243,127.14 138.719,127.14 137,128.859 137,132.75 137.264,133.013 138.242,133.013 139.699,133.912 139.699,134.704 139.841,134.885 140.472,134.883 140.547,134.797 140.547,131.444 139.382,130.73 139.387,130.091 139.915,129.747 157.195,129.738 160.325,133.523 160.325,152.14
+5V on Top Layer (solid, remove dead copper, pour order 4): 146.126,119.752 149.747,119.518 149.906,115.903 150.625,114.223 150.625,108.679 150.407,108.367 150.407,107.693 150.201,107.486 149.432,107.486 149.226,107.692 149.226,110.47 146.126,113.57
$1N27791 on Bottom Layer (solid, remove dead copper, pour order 40): 158.719,130.74 164.219,130.74 164.619,130.34 164.619,123.04 164.519,122.94 158.619,122.94 158.519,122.84 158.519,130.54
SW_1 on Top Layer (solid, remove dead copper, pour order 6): 135.861,122.267 141.276,122.267 142.148,121.394 142.148,117.156 141.603,116.468 135.742,116.468 134.29,117.921 134.29,120.695
$1N2164 on Bottom Layer (solid, remove dead copper, pour order 42): 178.419,132.9 184.759,132.9 184.759,119.883 178.419,119.88
VOUT1 on Top Layer (solid, remove dead copper, pour order 8): 147.266,105.804 148.587,105.804 148.985,106.437 149.3,106.805 151.963,106.805 152.136,106.632 152.136,104.645 151.811,104.319 149.168,104.319 148.686,104.819 147.326,104.819 147.226,104.919 147.226,105.765
OUT_BATT2 on Bottom Layer (solid, remove dead copper, pour order 44): 164.419,149.34 165.093,149.34 164.419,150.014
$2N28 on Top Layer (solid, remove dead copper, pour order 10): 175.39,150.945 179.913,150.945 179.981,143.921 179.099,143.04 175.958,143.04 175.39,144.119
OUT_BATT2 on Bottom Layer (solid, remove dead copper, pour order 46): 168.857,150.356 173.091,150.356 173.091,145.007 169.28,139.692 169.28,135.821 167.841,135.846 166.483,135.264 163.332,135.227 162.919,135.64 162.919,139.2 168.857,146.24
UBATT on Bottom Layer (solid, remove dead copper, pour order 48): 158.5,116.141 158.5,113.792 162.27,109.691 178.17,109.691 180.292,111.813 180.292,117.14 178.419,117.14 177.781,116.502 177.781,112.821 176.4,111.44 163.719,111.44 160.673,114.486 160.673,115.663 160,116.141
OUT_BATT on Top Layer (solid, remove dead copper, pour order 12): 165.771,104.62 165.771,128.775 159.945,128.72 162.804,125.233 162.904,104.547 163.761,103.689 164.84,103.689
OUT_BATT on Bottom Layer (solid, remove dead copper, pour order 50): 163.438,104.259 163.83,103.867 169.631,103.867 170.327,104.254 170.327,104.854 169.338,105.843 163.961,105.843 163.438,105.423
+5V on Top Layer (solid, remove dead copper, pour order 14): 128.919,123.956 128.919,126.018 129.682,126.376 148.186,126.376 149.919,124.643 149.919,120.198 148.604,118.883 146.572,118.883 146.064,119.391 146.064,122.566 145.175,123.455 129.692,123.455
+5V on Bottom Layer (solid, remove dead copper, pour order 52): 125.041,151.214 128.097,151.214 128.466,150.755 128.466,127.211 129.3,126.376 131.741,126.376 132.094,126.115 132.094,123.625 131.656,123.439 127.538,123.439 124.601,126.376 124.601,150.706
+5V on Top Layer (solid, remove dead copper, pour order 16): 103.315,150.914 103.68,151.268 128.36,151.268 128.907,150.721 128.907,148.969 128.284,148.347 124.578,148.347 123.181,149.744 103.518,149.744 103.315,150.05
+5V on Top Layer (solid, remove dead copper, pour order 18): 127.649,126.376 132.729,126.376 133.364,125.741 133.364,124.217 131.701,122.554 131.701,102.569 131.228,101.996 129.046,101.996 128.157,102.492 128.157,122.554 127.014,124.09
VOUT1 on Bottom Layer (solid, remove dead copper, pour order 54): 153.811,102.803 153.52,102.5 141.365,102.5 124.695,119.17 103.483,119.17 103.171,119.307 103.171,120.38 104.742,120.828 125.958,120.828 142.254,104.532 153.557,104.532 153.811,104.278
+5V on Top Layer (solid, remove dead copper, pour order 20): 103.174,112.916 103.748,113.293 127.522,113.293 128.919,114.69 128.919,110.372 128.792,110.245 127.522,111.515 103.799,111.515 103.174,111.864
+5V on Bottom Layer (solid, remove dead copper, pour order 56): 129.739,103.8 131.059,103.8 131.539,103.32 131.539,100.075 129.413,97.948 125.571,97.948 125.571,99.748 128.266,103.818 129.722,103.818
no net on Bottom Layer (solid, remove dead copper, pour order 58): 155.409,132.971 154.709,132.971 cw(c154.709,133.074) 154.607,133.074 154.607,133.974 cw(c154.709,133.974) 154.709,134.077 155.409,134.077 cw(c155.409,133.974) 155.512,133.974 155.512,133.074 cw(c155.409,133.074)
+5V on Top Layer (solid, remove dead copper, pour order 22): 124.536,150.855 125.676,151.995 132.876,151.995 133.716,151.155 133.716,146.054 124.994,146.054 124.536,146.522
no net on Bottom Layer (solid, remove dead copper, pour order 60): 155.409,132.971 154.709,132.971 cw(c154.709,133.074) 154.607,133.074 154.607,133.974 cw(c154.709,133.974) 154.709,134.077 155.409,134.077 cw(c155.409,133.974) 155.512,133.974 155.512,133.074 cw(c155.409,133.074)
+5V on Top Layer (solid, remove dead copper, pour order 24): 134.786,137.398 134.99,137.194 134.99,136.65 134.796,136.455 128.442,136.446 127.918,136.068 127.918,137.542 128.167,137.398
no net on Bottom Layer (solid, remove dead copper, pour order 62): 155.409,132.971 154.709,132.971 cw(c154.709,133.074) 154.607,133.074 154.607,133.974 cw(c154.709,133.974) 154.709,134.077 155.409,134.077 cw(c155.409,133.974) 155.512,133.974 155.512,133.074 cw(c155.409,133.074)
+5V on Top Layer (solid, remove dead copper, pour order 26): 103.28,143.768 120.462,143.727 122.064,142.125 122.064,139.204 123.334,137.934 127.525,137.934 128.033,137.426 128.033,135.775 127.652,135.394 122.826,135.394 119.778,138.442 119.778,141.229 119.061,142.157 103.835,142.157 103.18,142.62
no net on Bottom Layer (solid, remove dead copper, pour order 64): 154.607,133.074 154.607,133.974 cw(c154.709,133.974) 154.709,134.077 155.409,134.077 cw(c155.409,133.974) 155.512,133.974 155.512,133.074 cw(c155.409,133.074) 155.409,132.971 154.709,132.971 cw(c154.709,133.074)
+5V on Top Layer (solid, remove dead copper, pour order 28): 117.348,135.952 120.219,138.823 121.743,138.823 123.394,137.172 123.394,135.902 121.643,134.435 103.506,134.435 103.506,135.952
EN3V3 on Bottom Layer (solid, remove dead copper, pour order 66): 129.359,133.515 130.539,134.695 132.549,134.695 132.549,133.872 132.701,133.72 132.701,132.89 132.206,132.395 132.206,131.639 130.321,131.639 129.359,132.601
ADC1 on Top Layer (solid, remove dead copper, pour order 30): 103.3,128.22 113.98,128.22 114.4,127.8 114.4,127.26 114.1,126.96 103.6,126.96 103.3,127.26
+5V on Bottom Layer (solid, remove dead copper, pour order 68): 128.076,127.575 128.793,128.292 132.196,128.276 132.336,128.415 132.336,129.162 132.023,129.474 128.697,129.474 128.076,130.095
$2N30 on Top Layer (solid, remove dead copper, pour order 32): 188.932,151 193.032,151 193.032,143.949 192.158,143.075 189.927,143.075 188.932,144.07
+3V3 on Bottom Layer (solid, remove dead copper, pour order 70): 134.215,129.275 134.52,128.97 134.52,127.607 134.115,127.203 133.297,127.203 132.767,127.733 132.767,128.994 133.048,129.275
ISHUNT on Bottom Layer (solid, remove dead copper, pour order 72): 103.758,124.68 113.224,124.679 113.535,124.303 113.541,123.171 112.816,122.983 103.909,122.931 103.42,123.42 103.42,124.38
+5V on Bottom Layer (solid, remove dead copper, pour order 74): 103.18,105.12 103.72,105.66 118.874,105.66 124.171,100.193 128.332,99.092 128.332,98.1 123.979,98.1 118.105,104.04 103.6,104.04 103.3,104.34 103.3,105
no net on Bottom Layer (solid, remove dead copper, pour order 76): 136.547,145.557 136.73,145.74 137.7,145.74 137.76,145.68 137.586,145.506 137.586,144.526 137.22,144.16 137.22,144.12 137.18,144.16 136.738,144.16 136.738,145.322 136.62,145.44 136.62,145.484

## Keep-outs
Bottom Layer:
  region: 132.276,129.675 134.256,129.675 134.256,129.555 134.196,129.495 132.516,129.495 132.456,129.555 132.396,129.555
Board Outline Layer:
  lines w0.254: 101.52,92.34 195.52,92.34 195.52,157.52 101.52,157.52 101.52,92.34
Multi-Layer:
  circle w0.254: c119.915,137.723 r1.25
  circle w0.254: c119.932,114.836 r1.25
  circle w0.254: c119.915,137.723 r1.552
  region: 138.139,136.24 142.439,136.24 142.439,141.289 138.139,141.289
  region: 144.313,105.995 148.176,105.995 148.176,110.325 144.313,110.325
